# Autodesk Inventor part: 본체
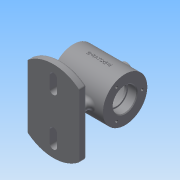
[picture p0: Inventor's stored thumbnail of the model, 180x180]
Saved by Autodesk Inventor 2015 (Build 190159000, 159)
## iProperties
Created: 2017-12
Part Number: 본체
Material: 일반
Document SubType Name: Modeling
Designer: Administrator
Density: 1 g/cm^3
Appearance: 기본값
Author: Administrator
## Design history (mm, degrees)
sketch "스케치5"
  geometry: L1 (35, -42.426)-(35, 42.426); L2 (-35, 42.426)-(-35, -42.426); A1 r 55 centre (0, 0) between (35, 42.426) and (-35, 42.426); A2 r 55 centre (0, 0) between (-35, -42.426) and (35, -42.426); 1 further point
  constraints: 4 end point, 4 point on circle, 2 centre point, 2 vertical, 1 coincident
  dimensions: "d1" = 35 distance from line of point (0, 0) L1; "d2" = 70 distance between parallel lines of L2 L1; "d3" = 55 radius of A2; "d4" = 55 radius of A1
extrude "돌출1" new body sketch "스케치5" distance "d5" = 10; taper "d6" = 0 deg
fillet "모깎기1" dims "d7" = 3
fillet "모깎기2" dims "d8" = 3
sketch "스케치6"
  geometry: C1 r 30 at (62, 0); 1 further point
  constraints: 1 centre point, 1 horizontal alignment
  dimensions: "d9" = 60 diameter of C1; "d10" = 62 distance of point (0, 0) C1.centre
extrude "돌출2" join sketch "스케치6" stored distance "d11" = 70; taper "d12" = 0 deg
node "작업 평면1"
sketch "스케치7"
  geometry: C1 r 8 at (0, 0); 1 further point
  constraints: 1 centre point, 1 coincident
  dimensions: "d14" = 16 diameter of C1
extrude "돌출3" join sketch "스케치7" distance "d15" = 37; taper "d16" = 0 deg
fillet "모깎기3" dims "d17" = 3
sketch "스케치9"
  geometry: L1 (-35, 78)-(-23.3, 78); L2 (-23, 77.7)-(-23, 76); L3 (-23, 76)-(-20, 76); L4 (-20, 76)-(-20, 84); L5 (-17, 87)-(17, 87); L6 (20, 84)-(20, 76); L7 (20, 76)-(23, 76); L8 (23, 76)-(23, 77.7); L9 (23.3, 78)-(35, 78); L10 (-35, 62)-(35, 62); L11 (-35, 92)-(-35, 32) reference; L12 (35, 32)-(35, 92) reference; L13 (-35, 78)-(-35, 62); L14 (35, 78)-(35, 62); A1 r 3 centre (17, 84) between (20, 84) and (17, 87); A2 r 3 centre (-17, 84) between (-17, 87) and (-20, 84); A3 r 0.3 centre (-23.3, 77.7) between (-23, 77.7) and (-23.3, 78); A4 r 0.3 centre (23.3, 77.7) between (23.3, 78) and (23, 77.7); 5 further points
  constraints: 24 end point, 10 point on line, 8 perpendicular, 8 point on circle, 8 tangent, 4 centre point, 2 equal radius, 2 horizontal, 2 midpoint, 1 collinear, 1 vertical
  dimensions: "d18" = 62 distance from line of point (0, 0) L10; "d19" = 16 distance between parallel lines of L10 L1; "d20" = 14 distance between parallel lines of L10 L3; "d21" = 25 distance between parallel lines of L10 L5; "d22" = 14 distance between parallel lines of L10 L7; "d23" = 16 distance between parallel lines of L10 L9; "d24" = 12 distance between parallel lines of L2 L11; "d25" = 12 distance between parallel lines of L12 L8; "d26" = 3 distance of L6.end L7.end; "d28" = 40 distance between parallel lines of L6 L4; "d30" = 3 radius of A1; "d31" = 0.3 radius of A3
revolve "회전1" stored, may be unused: angle "d29" = 90 deg
chamfer "모따기1" distance "d32" = 1; stored, may be unused: second distance "d33" = 2, angle "d34" = 45 deg
sketch "스케치10" dims "d35" = 46
  geometry: C1 r 30 at (0, 0) reference; C2 r 17 at (0, 0) reference; 3 further points
  constraints: 2 vertical alignment, 1 coincident, 2 other
hole "구멍1" sketch "스케치10" at (0, 23) diameter "d36" = 3.459; stored, may be unused: countersink angle "d40" = 90 deg, drill point angle "d42" = 118 deg; dims "d37" = 8, "d38" = 4, "d39" = 2, "d41" = 10
node "작업 평면2"
sketch "스케치11"
  geometry: C1 r 8 at (0, 0) reference; C2 r 4 at (0, 0)
  constraints: 1 centre point, 1 coincident
  dimensions: "d46" = 8 diameter of C2
extrude "돌출4" cut sketch "스케치11" distance "d47" = 37; taper "d48" = 0 deg
chamfer "모따기2" distance "d49" = 1; stored, may be unused: second distance "d50" = 2, angle "d51" = 45 deg
sketch "스케치12"
  geometry: L1 (-15, 0)-(15, 0); L2 (-15, -5)-(15, -5); L3 (15, 5)-(-15, 5); L4 (0, 40)-(0, 24); L5 (-5, 40)-(-5, 24); L6 (5, 24)-(5, 40); A1 r 52 centre (0, 0) between (32, 40.988) and (-32, 40.988) reference; A2 r 52 centre (0, 0) between (-32, -40.988) and (32, -40.988) reference; A3 r 5 centre (-15, 0) between (-15, 5) and (-15, -5); A4 r 5 centre (15, 0) between (15, -5) and (15, 5); A5 r 5 centre (0, 40) between (5, 40) and (-5, 40); A6 r 5 centre (0, 24) between (-5, 24) and (5, 24); 1 further point
  constraints: 16 end point, 8 point on circle, 8 tangent, 4 centre point, 2 midpoint, 2 parallel, 1 horizontal, 1 vertical, 1 vertical alignment
  dimensions: "d52" = 30 distance of L1.start L1.end; "d53" = 5 radius of A3; "d54" = 16 distance of L4.start L4.end; "d55" = 24 distance of A2.centre L4.end; "d56" = 5 radius of A5
extrude "돌출5" join sketch "스케치12" distance "d57" = 52; taper "d58" = 0 deg
revolve "회전2" stored, may be unused: angle "d59" = 90 deg
extrude "돌출6" cut sketch "스케치12" distance "d60" = 52; taper "d61" = 0 deg
fillet "모깎기4" dims "d62" = 5
node "작업 평면3"
sketch "스케치13"
  geometry: L1 (-35, 92)-(-35, 32) reference; L2 (-35, 92)-(35, 92) reference; 2 further points
  constraints: 1 other
  dimensions: "d64" = 30 distance from line of L2 point (0, 62); "d65" = 35 distance from line of L1 point (0, 62)
feature "엠보싱1" sketch "스케치13" dims "d1" = 35, "d2" = 70, "d3" = 55, "d4" = 55, "d66" = 0.5, "d67" = 0
node "솔리드1"
pattern_circular "원형 패턴1" dims angle "d44" = 360 deg
mirror "대칭1"
mirror "대칭2"
other parameters: "d13" = 62, "d63" = 69.5
